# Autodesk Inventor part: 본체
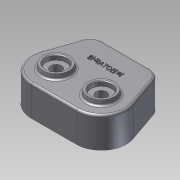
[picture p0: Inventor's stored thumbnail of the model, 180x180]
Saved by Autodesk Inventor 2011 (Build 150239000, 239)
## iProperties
Created: 2014-12
Part Number: 본체
Document SubType Name: Modeling
Designer: SDA
Density: 1 g/cm^3
Author: SDA
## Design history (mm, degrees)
sketch "스케치1"
  geometry: L1 (-34.162, 36)-(34.162, 36); L2 (0, 0)-(-32.527, -32.527); L3 (0, 0)-(32.527, -32.527); L4 (0, 60.781)-(0, -67.298); L5 (-51.181, 23.862)-(-66.565, -20.803); L6 (51.181, 23.862)-(66.565, -20.803); L7 (-32.527, -68.527)-(32.527, -68.527); A1 r 46 centre (0, 0) between (-32.527, -32.527) and (32.527, -32.527); A2 r 18 centre (-34.162, 18) between (-34.162, 36) and (-51.181, 23.862); A3 r 18 centre (34.162, 18) between (51.181, 23.862) and (34.162, 36); A4 r 36 centre (-32.527, -32.527) between (-66.565, -20.803) and (-32.527, -68.527); A5 r 36 centre (32.527, -32.527) between (32.527, -68.527) and (66.565, -20.803); 4 further points
  constraints: 14 end point, 10 point on circle, 7 tangent, 5 centre point, 4 coincident, 4 point on line, 2 perpendicular, 1 equal radius, 1 horizontal, 1 midpoint, 1 vertical alignment
  dimensions: "d0" = 94 distance of point (-47, 36) point (47, 36); "d4" = 92 diameter of A1; "d5" = 36 distance from line of point (0, 0) L1; "d7" = 45 deg angle of L4 L2; "d8" = 45 deg angle of L3 L4; "d12" = 18 radius of A2; "d13" = 36 radius of A5; "d14" = 36 radius of A4
extrude "돌출1" new body sketch "스케치1" distance "d15" = 44; taper "d16" = 0 deg
feature "쉘1" dims "d17" = 5
sketch "스케치2"
  geometry: C1 r 24 at (34.162, -31); C2 r 24 at (1.635, -63.527); C3 r 24 at (66.689, -63.527); A1 r 31 centre (1.635, -63.527) between (-27.675, -53.432) and (1.635, -94.527) reference; A2 r 31 centre (66.689, -63.527) between (66.689, -94.527) and (95.999, -53.432) reference; 1 further point
  constraints: 3 centre point, 3 coincident
  dimensions: "d18" = 48 diameter of C1; "d19" = 48 diameter of C2; "d20" = 48 diameter of C3
extrude "돌출2" join sketch "스케치2" distance "d21" = 16; taper "d22" = 0 deg
sketch "스케치3"
  geometry: L1 (-61.837, -22.432)-(-46.453, 22.233) reference; L2 (46.453, 22.233)-(61.837, -22.432) reference; L3 (32.527, -63.527)-(-32.527, -63.527) reference; L4 (-66.565, -20.803)-(-51.181, 23.862) reference; L5 (32.527, -68.527)-(-32.527, -68.527) reference; L6 (51.181, 23.862)-(66.565, -20.803) reference; L7 (-34.162, 36)-(34.162, 36) reference; L8 (-72.125, 7)-(77.004, 7); L9 (0, 60.781)-(0, -67.298) reference; L10 (-32.527, -63.527)-(32.527, -63.527) reference; A1 r 8 centre (-51.7, 7) between (-58.461, 2.724) and (-54.394, 14.533); A2 r 8 centre (0, -63.527) between (6.245, -68.527) and (-6.245, -68.527); A3 r 8 centre (51.7, 7) between (54.394, 14.533) and (58.461, 2.724); 1 further point
  constraints: 10 point on line, 6 point on circle, 3 centre point, 2 end point, 1 midpoint, 1 parallel
  dimensions: "d23" = 29 distance between parallel lines of L8 L7; "d24" = 16 diameter of A1; "d25" = 16 diameter of A2; "d26" = 16 diameter of A3
extrude "돌출3" join sketch "스케치3" stored distance "d27" = 11; taper "d28" = 0 deg
hole "Hole1" diameter "d31" = 35; stored, may be unused: countersink angle "d35" = 90 deg, drill point angle "d37" = 0 deg; dims "d29" = 10, "d30" = 10, "d32" = 6, "d33" = 4, "d34" = 2, "d36" = 11
hole "Hole2" diameter "d40" = 35; stored, may be unused: countersink angle "d44" = 90 deg, drill point angle "d46" = 0 deg; dims "d38" = 10, "d39" = 10, "d41" = 6, "d42" = 4, "d43" = 2, "d45" = 11
hole "Hole3" diameter "d49" = 15.5; stored, may be unused: countersink angle "d53" = 90 deg, drill point angle "d55" = 0 deg; dims "d47" = 10, "d48" = 10, "d50" = 6, "d51" = 4, "d52" = 2, "d54" = 10
hole "Hole4" diameter "d58" = 15.5; stored, may be unused: countersink angle "d62" = 90 deg, drill point angle "d64" = 0 deg; dims "d56" = 10, "d57" = 10, "d59" = 6, "d60" = 4, "d61" = 2, "d63" = 10
sketch "스케치4"
  geometry: C1 r 20 at (-32.527, -32.527); C2 r 20 at (32.527, -32.527); A1 r 36 centre (32.527, -32.527) between (32.527, -68.527) and (66.565, -20.803) reference; A2 r 36 centre (-32.527, -32.527) between (-66.565, -20.803) and (-32.527, -68.527) reference; 1 further point
  constraints: 2 centre point, 2 coincident
  dimensions: "d65" = 40 diameter of C1; "d66" = 40 diameter of C2
extrude "돌출4" join sketch "스케치4" distance "d67" = 7; taper "d68" = -10 deg
hole "Hole5" diameter "d71" = 30; stored, may be unused: countersink angle "d75" = 90 deg, drill point angle "d77" = 0 deg; dims "d69" = 10, "d70" = 10, "d72" = 6, "d73" = 4, "d74" = 2, "d76" = 7
hole "Hole6" diameter "d80" = 30; stored, may be unused: countersink angle "d84" = 90 deg, drill point angle "d86" = 0 deg; dims "d78" = 10, "d79" = 10, "d81" = 6, "d82" = 4, "d83" = 2, "d85" = 7
hole "Hole7" diameter "d89" = 40; stored, may be unused: countersink angle "d93" = 90 deg, drill point angle "d95" = 0 deg; dims "d87" = 10, "d88" = 10, "d90" = 6, "d91" = 4, "d92" = 2, "d94" = 12
hole "Hole8" diameter "d98" = 20; stored, may be unused: countersink angle "d102" = 90 deg, drill point angle "d104" = 0 deg; dims "d96" = 10, "d97" = 10, "d99" = 6, "d100" = 4, "d101" = 2, "d103" = 3
fillet "모깎기1" dims "d105" = 3
hole "Hole9" diameter "d108" = 4.134; stored, may be unused: countersink angle "d112" = 90 deg, drill point angle "d114" = 118 deg; dims "d106" = 10, "d107" = 10, "d109" = 20, "d110" = 4, "d111" = 2, "d113" = 23
hole "Hole10" diameter "d117" = 4.134; stored, may be unused: countersink angle "d121" = 90 deg, drill point angle "d123" = 118 deg; dims "d115" = 10, "d116" = 10, "d118" = 20, "d119" = 4, "d120" = 2, "d122" = 23
hole "Hole11" diameter "d126" = 4.134; stored, may be unused: countersink angle "d130" = 90 deg, drill point angle "d132" = 118 deg; dims "d124" = 10, "d125" = 10, "d127" = 20, "d128" = 4, "d129" = 2, "d131" = 23
chamfer "모따기1" distance "d136" = 1; stored, may be unused: second distance "d137" = 2, angle "d138" = 45 deg
sketch "스케치5"
  geometry: 1 further point
sketch "스케치6"
  geometry: L1 (-20.143, -31.564)-(-27.675, -53.432) reference; L2 (1.635, -94.527)-(26.162, -94.527) reference; L3 (42.162, -94.527)-(66.689, -94.527) reference; L4 (95.999, -53.432)-(88.467, -31.564) reference; L5 (83.257, -16.436)-(80.615, -8.767) reference; L6 (68.324, 0)-(0, 0) reference; L7 (-12.291, -8.767)-(-14.933, -16.436) reference; A1 r 8 centre (-17.538, -24) between (-20.143, -31.564) and (-14.933, -16.436) reference; A2 r 31 centre (1.635, -63.527) between (-27.675, -53.432) and (1.635, -94.527) reference; A3 r 8 centre (34.162, -94.527) between (42.162, -94.527) and (26.162, -94.527) reference; A4 r 31 centre (66.689, -63.527) between (66.689, -94.527) and (95.999, -53.432) reference; A5 r 8 centre (85.862, -24) between (83.257, -16.436) and (88.467, -31.564) reference; A6 r 13 centre (68.324, -13) between (80.615, -8.767) and (68.324, 0) reference; A7 r 13 centre (0, -13) between (0, 0) and (-12.291, -8.767) reference; A8 r 24 centre (34.162, -31) between (55.273, -42.416) and (13.051, -42.416) reference; A9 r 24 centre (66.689, -63.527) between (45.578, -52.111) and (55.273, -42.416) reference; A10 r 24 centre (34.162, -31) between (22.746, -52.111) and (45.578, -52.111) reference; A11 r 24 centre (1.635, -63.527) between (13.051, -42.416) and (22.746, -52.111) reference
extrude "돌출5" join sketch "스케치6" distance "d139" = 5; taper "d140" = 0 deg
fillet "모깎기3" dims "d141" = 3
sketch "스케치10"
  geometry: 1 further point
fillet "모깎기4" dims "d142" = 0.3, "d143" = 0.1
sketch "스케치11"
  geometry: L1 (34.162, 36)-(-34.162, 36) reference; 2 further points
  constraints: 1 vertical alignment, 1 other
  dimensions: "d144" = 30 distance from line of point (0, 6) L1
feature "엠보싱1" sketch "스케치11" dims "d145" = 1, "d146" = 0
node "솔리드1"
other parameters: "d10" = 72, "d11" = 72
